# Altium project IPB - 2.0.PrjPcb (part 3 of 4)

## Sheet Anti_Alias_Filter.SchDoc: MARS2 - IPB - Anti-Alias Filter
size 431 x 279 mm; Organization: ORGANIZATION; Address1: APPLIED PHYSICS LAB; Address2: UNIVERSITY OF WASHINGTON; Address3: 1013 NE 40TH STREET; Address4: SEATTLE, WA 98105; Revision: -; SheetNumber: 18; SheetTotal: 23; ENG_APP_DATE: --/--/--; DSN_APP_DATE: --/--/--; CHK_APP_DATE: --/--/--
Used 4 times, as channels Designator/Interface Channel A/Anti-Alias Filter, Designator/Interface Channel B/Anti-Alias Filter, Designator/Interface Channel C/Anti-Alias Filter, Designator/Interface Channel D/Anti-Alias Filter. Parts and nets are listed once, with the designators drawn on the sheet.
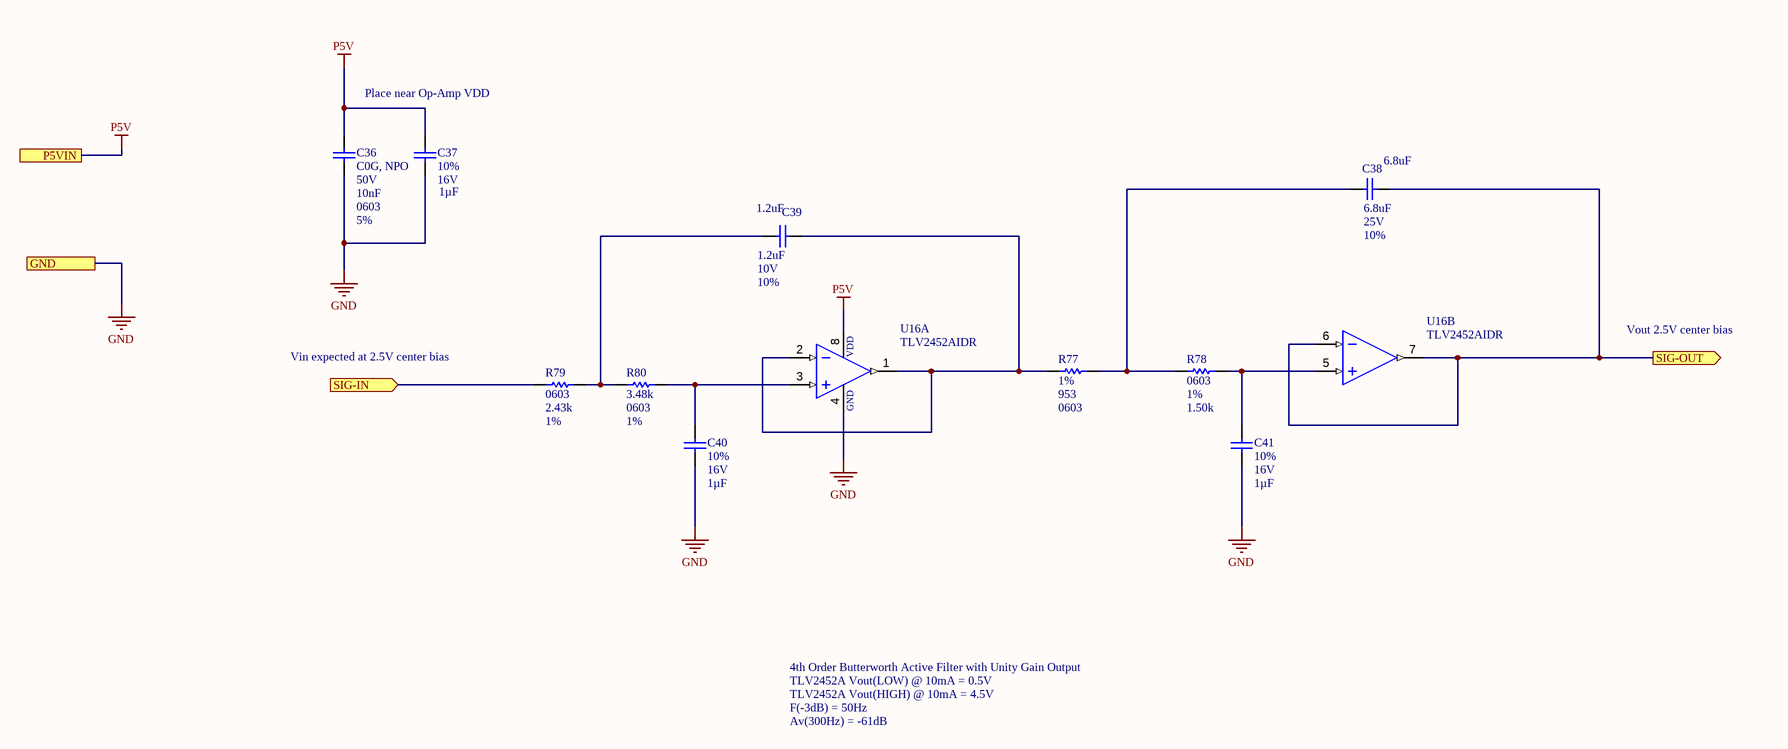
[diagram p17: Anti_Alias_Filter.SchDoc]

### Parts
C36  Dielectric: C0G, NPO  Voltage Rating: 50V  Capacitance: 10nF  Case/Package: 0603  Tolerance: 5%  [CAPC1608X90X40ML10T20]  (hidden comment: Capacitor 10nF +/- 5%, 50V, C0G, 0603)
C37  value 1µF  Tolerance: 10%  Voltage Rating: 16V  [CAPC1608X94X35NL15T15]  (hidden comment: Capacitor 1 uF +/- 10% 16 V 0603)
C38  value 6.8uF  Voltage Rating: 25V  Tolerance: 10%  Capacitance: 6.8uF  [FP-CGA5L-0_3-0_1-IPC_A]  (hidden comment: CGA5L1X7R1E685K160AC)
C39  value 1.2uF  Tolerance: 10%  Voltage Rating (DC): 10V  Capacitance: 1.2uF  [CAPC2012X11M]  (hidden comment: C0805C125K8RAC7800)
C40  value 1µF  Tolerance: 10%  Voltage Rating: 16V  [CAPC1608X94X35NL15T15]  (hidden comment: Capacitor 1 uF +/- 10% 16 V 0603)
C41  value 1µF  Tolerance: 10%  Voltage Rating: 16V  [CAPC1608X94X35NL15T15]  (hidden comment: Capacitor 1 uF +/- 10% 16 V 0603)
R77  value 953  Tolerance: 1%  Case/Package: 0603  [RESC1608X55X25ML10T15]  (hidden comment: Resistor 953R +/-1% 0603 100 mW)
R78  value 1.50k  Case/Package: 0603  Tolerance: 1%  [RESC1608X55X25ML10T15]  (hidden comment: Resistor 1K50+/-1% 0603 100 mW)
R79  value 2.43k  Case/Package: 0603  Tolerance: 1%  [RESC1608X55X25ML10T15]  (hidden comment: Resistor 2K43+/-1% 0603 100 mW)
R80  value 3.48k  Case/Package: 0603  Tolerance: 1%  [RESC1608X55X25ML10T15]  (hidden comment: Resistor 3K48+/-1% 0603 100 mW)
U16  TLV2452AIDR  [D0008A_L]  (parts A,B of 2)

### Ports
GND, P5VIN, SIG-IN (in), SIG-OUT (out)

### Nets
GND: C36.2 C37.1 C40.1 C41.1 U16.4(GND) ; port GND
P5V: C36.1 C37.2 U16.8(VDD+) ; port P5VIN
SIG-IN: R79.1 ; port SIG-IN
SIG-OUT: C38.1 U16.6(IN2-) U16.7(OUT2) ; port SIG-OUT
NetC38_2: C38.2 R77.2 R78.1
NetC39_1: C39.1 R79.2 R80.1
NetC39_2: C39.2 R77.1 U16.1(OUT1) U16.2(IN1-)
NetC40_2: C40.2 R80.2 U16.3(IN1+)
NetC41_2: C41.2 R78.2 U16.5(IN2+)

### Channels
Designator/Interface Channel A/Anti-Alias Filter: designators end in _A; ports GND=LV_GND P5VIN=LV_P5V SIG-IN=CH-I_Interface Channel A SIG-OUT=CHA_I
Designator/Interface Channel B/Anti-Alias Filter: designators end in _B; ports GND=LV_GND P5VIN=LV_P5V SIG-IN=CH-I_Interface Channel B SIG-OUT=CHB_I
Designator/Interface Channel C/Anti-Alias Filter: designators end in _C; ports GND=LV_GND P5VIN=LV_P5V SIG-IN=CH-I_Interface Channel C SIG-OUT=CHC_I
Designator/Interface Channel D/Anti-Alias Filter: designators end in _D; ports GND=LV_GND P5VIN=LV_P5V SIG-IN=CH-I_Interface Channel D SIG-OUT=CHD_I

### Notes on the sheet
- Place near Op-Amp VDD
- Vout 2.5V center bias
- Vin expected at 2.5V center bias
- 4th Order Butterworth Active Filter with Unity Gain Output
- TLV2452A Vout(LOW) @ 10mA = 0.5V
- TLV2452A Vout(HIGH) @ 10mA = 4.5V
- F(-3dB) = 50Hz
- Av(300Hz) = -61dB

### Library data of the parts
C36 = CMP-001-00166-10: Chip Capacitor, 10nF, +/- 5%, 50 V, C0G 0603 (1608 Metric); Capacitor Type: Ceramic
C37 C40 C41 = CMP-001-00003-15: Chip Capacitor, 1 uF, +/- 10%, 16 V, 0603 (1608 Metric); Capacitor Type: Ceramic; Decade: 1uF
C38 = CMP-001-00094-9: Cap Ceramic 6.8uF 25V X7R 10% SMD 1206 125°C Blister Plastic T/R; Manufacturer: TDK; Decade: 1uF
C39 = CMP-001-00093-9: Cap Ceramic 1.2uF 10V X7R 10% SMD 0805 125°C Plastic T/R; Manufacturer: KEMET; Decade: 1uF
R77 = CMP-009-00692-4: Chip Resistor, 953 Ohm, +/- 1%, 0.1 W, -55 to 155 degC, 0603 (1608 Metric); Decade: 100; Power: 100mW; Voltage Rating: 75V
R78 = CMP-009-00693-3: Chip Resistor, 1.50 KOhm, +/- 1%, 0.1 W, -55 to 155 degC, 0603 (1608 Metric); Voltage Rating: 75V; Decade: 1k; Power: 100mW
R79 = CMP-009-00594-3: Chip Resistor, 2.43 KOhm, +/- 1%, 0.1 W, -55 to 155 degC, 0603 (1608 Metric); Power: 100mW; Decade: 1k; Voltage Rating: 75V
R80 = CMP-009-00691-3: Chip Resistor, 3.48 KOhm, +/- 1%, 0.1 W, -55 to 155 degC, 0603 (1608 Metric); Decade: 1k; Power: 100mW; Voltage Rating: 75V
U16 = CMP-014-00006-4: TLV2452A Dual 23-UA 220-KHZ Rail; Gain Bandwidth Product: 220kHz; Input Bias Current: 5nA; Voltage Gain: 103dB; Max Supply Voltage: 6V; Max Power Dissipation: 710mW; Min Dual Supply Voltage: 1.35V; Slew Rate: 0.11V/µs; Min Supply Voltage: 2.7V; Output Current: 10mA; Max Dual Supply Voltage: 3V; Nominal Supply Current: 84uA; Number of Channels: 2; Amplifier Type: GENERAL PURPOSE; Common Mode Rejection Ratio: 70dB; Input Offset Voltage (Vos): 1mV

## Sheet Solid_State_Switch.SchDoc: MARS2 - IPB - HV Solid State Switches
size 431 x 279 mm; Address1: APPLIED PHYSICS LAB; Address2: UNIVERSITY OF WASHINGTON; Address3: 1013 NE 40TH STREET; Address4: SEATTLE, WA 98105; SheetNumber: 19; SheetTotal: 23; ENG_APP_DATE: --/--/--; DSN_APP_DATE: --/--/--; CHK_APP_DATE: --/--/--; SPICEModelCacheBYHFRFMZ: <root> / <DocumentId>BYHFRFMZ</DocumentId> / </root>
Used 4 times, as channels Designator/Interface Channel A/Solid State Switches, Designator/Interface Channel B/Solid State Switches, Designator/Interface Channel C/Solid State Switches, Designator/Interface Channel D/Solid State Switches. Parts and nets are listed once, with the designators drawn on the sheet.
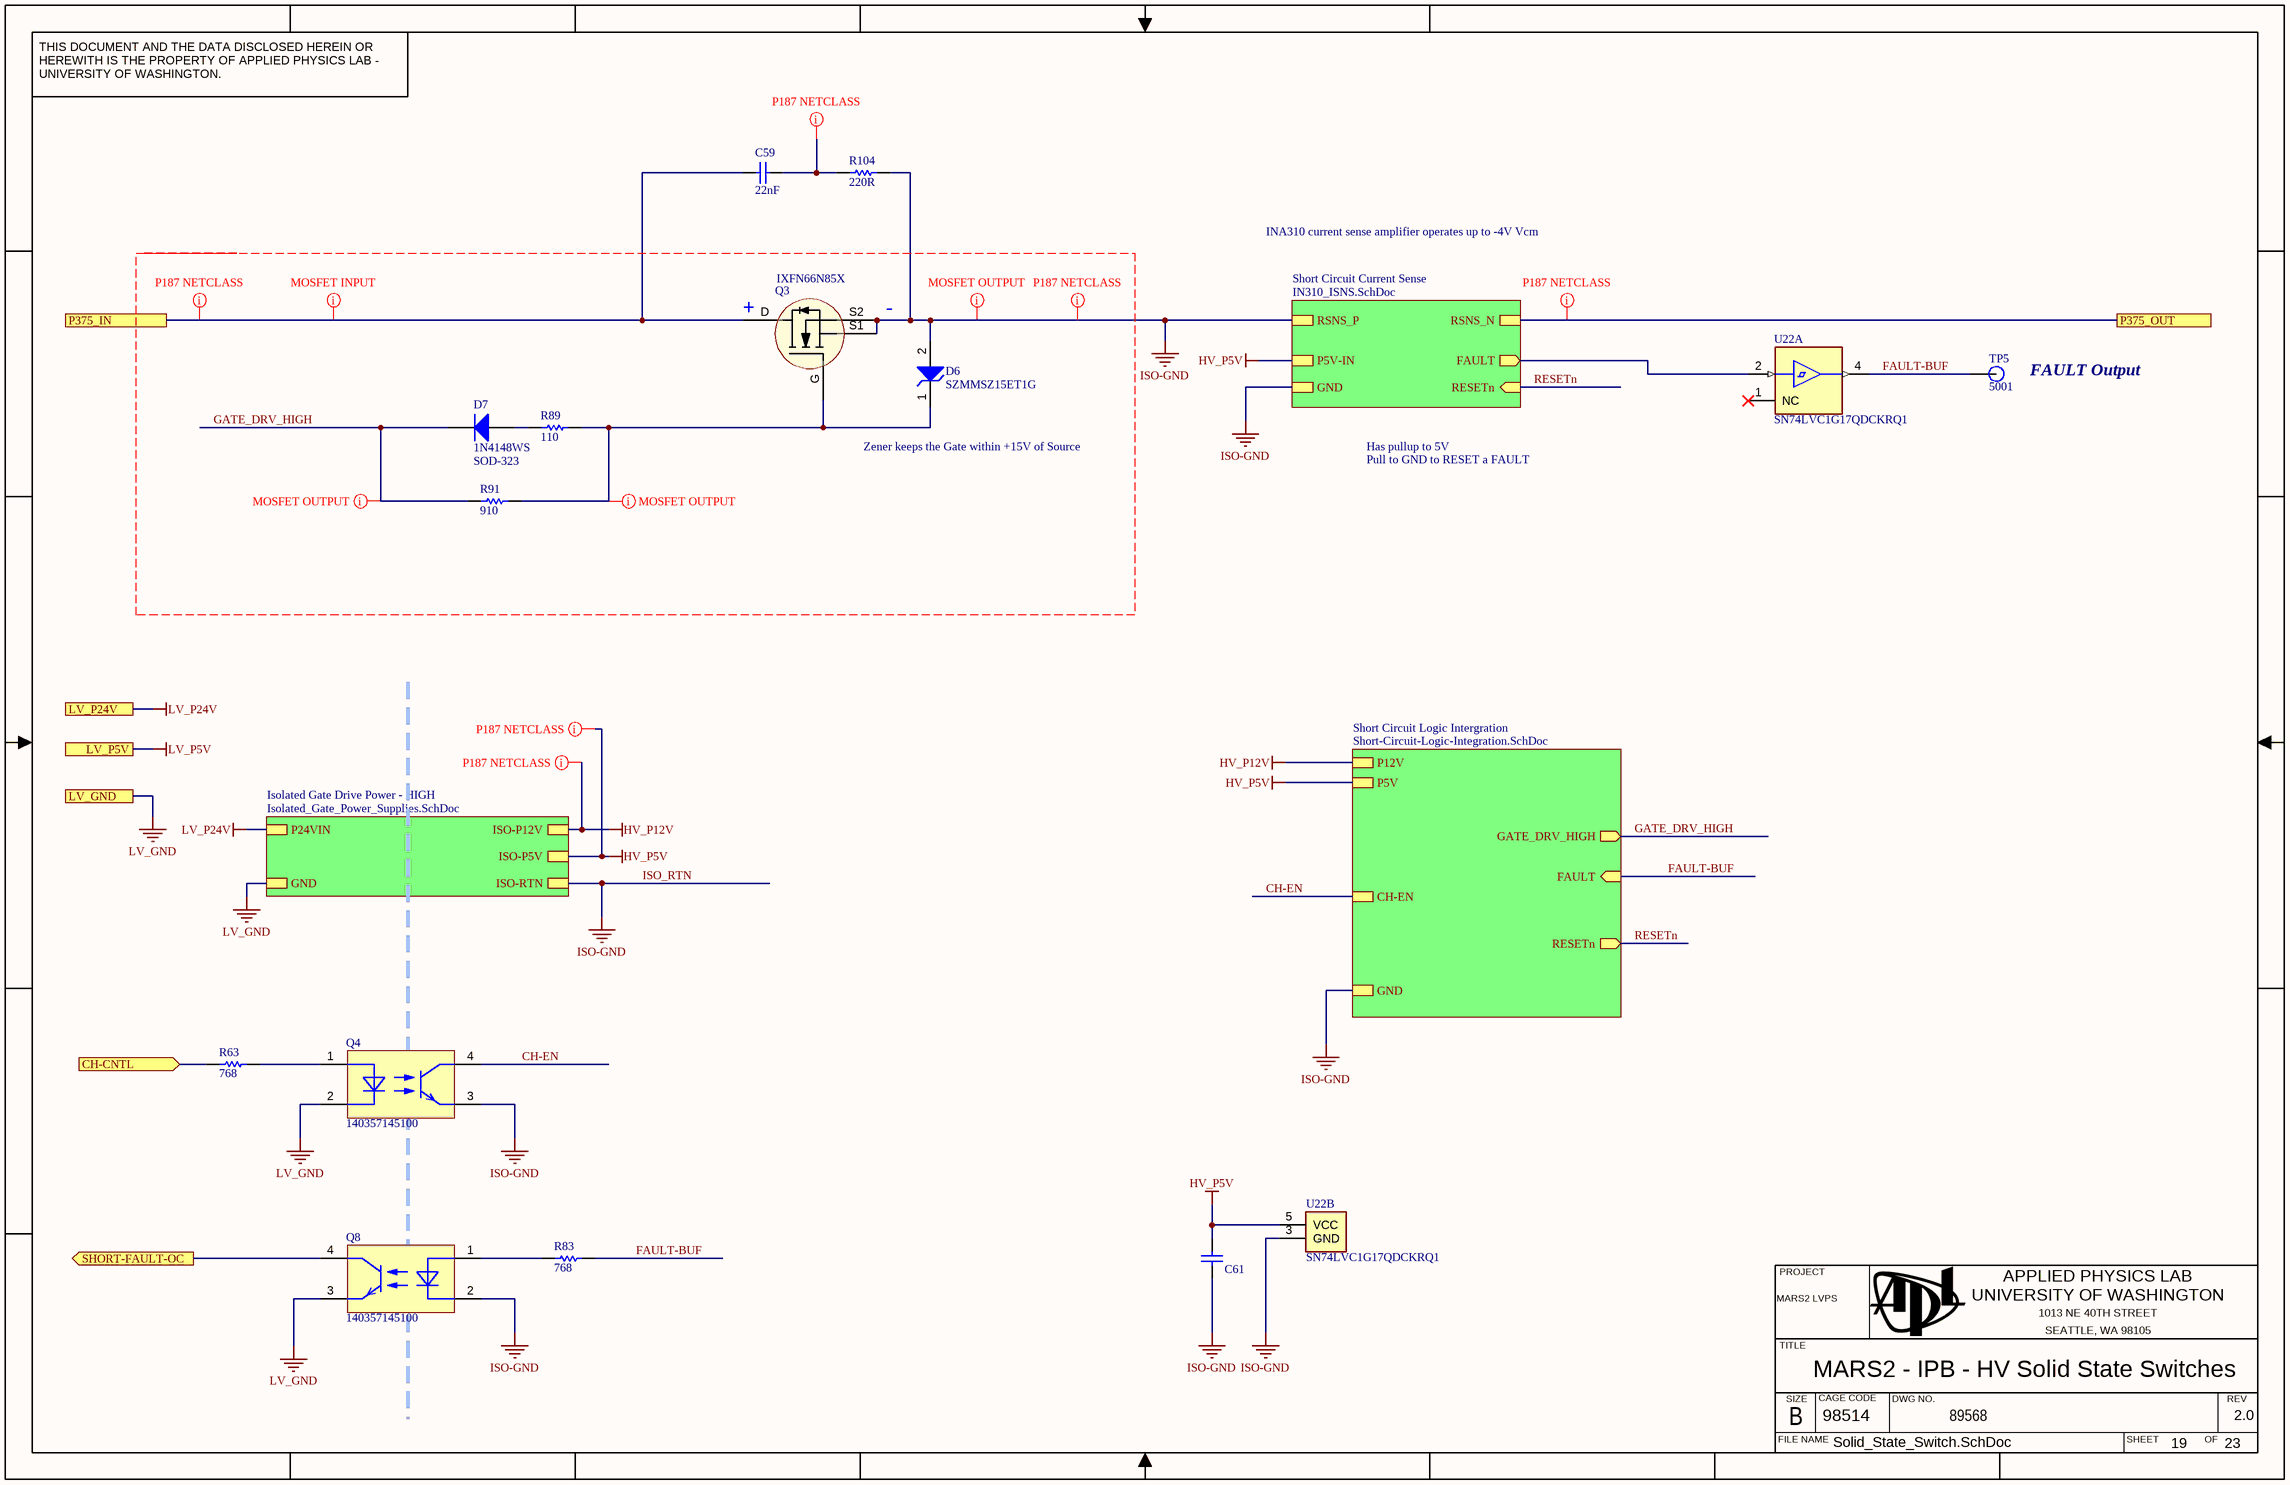
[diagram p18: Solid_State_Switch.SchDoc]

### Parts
C59  value 22nF  [R76QI222050H4J-Footprint-1]  (hidden comment: R76QI222050H4J)
C61  885012207072  [WCAP-CSGP_0805_L2W1.25H0.8_Reflow]  (value not drawn)
D6  SZMMSZ15ET1G  [ONSC-SOD-123-2-425-04_V]
D7  1N4148WS  Case/Package: SOD-323  [FAIR-SOD-323_V]
Q3  IXFN66N85X  [IXFN66N85X-Footprint-1]
Q4  140357145100  [WL-OCPT_SOP4]
Q8  140357145100  [WL-OCPT_SOP4]
R63  value 768  [PANASONIC_ERJ6E]  (hidden comment: RES 0805 768R 1%)
R83  value 768  [PANASONIC_ERJ6E]  (hidden comment: RES 0805 768R 1%)
R89  value 110  [PANASONIC_ERJ6E]  (hidden comment: RES 0805 110R 1%)
R91  value 910  [PANASONIC_ERJ6E]  (hidden comment: RES 0805 910R 1%)
R104  value 220R  [RESC3126X06M]  (hidden comment: RPC2010JT220R)
TP5  5001  [Keystone 5001]
U22  SN74LVC1G17QDCKRQ1  [FP-DCK0005A-MFG]  (parts A,B of 2)

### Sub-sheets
Isolated Gate Drive Power - HIGH = Isolated_Gate_Power_Supplies.SchDoc: ISO-RTN, ISO-P12V, ISO-P5V, GND, P24VIN
Short Circuit Current Sense = IN310_ISNS.SchDoc: RSNS_P, RSNS_N, P5V-IN, GND, FAULT (out), RESETn (in)
Short Circuit Logic Intergration = Short-Circuit-Logic-Integration.SchDoc: GND, P5V, RESETn (out), FAULT (in), P12V, GATE_DRV_HIGH (out), CH-EN

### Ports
CH-CNTL (in), LV_GND, LV_P5V, LV_P24V, P375_IN, P375_OUT, SHORT-FAULT-OC (out)

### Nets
HV_P5V: C61.2 U22.5(VCC) ; sheet Isolated Gate Drive Power - HIGH/ISO-P5V, sheet Short Circuit Current Sense/P5V-IN, sheet Short Circuit Logic Intergration/P5V
HV_P12V: sheet Isolated Gate Drive Power - HIGH/ISO-P12V, sheet Short Circuit Logic Intergration/P12V
ISO_RTN: C61.1 D6.2(A) Q3.S1 Q3.S2 Q4.3(Emitter) Q8.2(Cathode) R104.2 U22.3(GND) ; sheet Isolated Gate Drive Power - HIGH/ISO-RTN, sheet Short Circuit Current Sense/RSNS_P, sheet Short Circuit Current Sense/GND, sheet Short Circuit Logic Intergration/GND  [also labelled ISO-GND]
LV_GND: Q4.2(Cathode) Q8.3(Emitter) ; port LV_GND, sheet Isolated Gate Drive Power - HIGH/GND
LV_P24V: port LV_P24V, sheet Isolated Gate Drive Power - HIGH/P24VIN
CH-CNTL: R63.1 ; port CH-CNTL
CH-EN: Q4.4(Collector) ; sheet Short Circuit Logic Intergration/CH-EN
FAULT-BUF: R83.2 TP5.1 U22.4(Y) ; sheet Short Circuit Logic Intergration/FAULT
GATE_DRV_HIGH: D7.2(K) R91.1 ; sheet Short Circuit Logic Intergration/GATE_DRV_HIGH
P375_IN: C59.1 Q3.D ; port P375_IN
P375_OUT: port P375_OUT, sheet Short Circuit Current Sense/RSNS_N
RESETn: sheet Short Circuit Current Sense/RESETn, sheet Short Circuit Logic Intergration/RESETn
SHORT-FAULT-OC: Q8.4(Collector) ; port SHORT-FAULT-OC
NetC59_2: C59.2 R104.1
NetD6_1: D6.1(K) Q3.G R89.2 R91.2
NetD7_1: D7.1(A) R89.1
NetQ4_1: Q4.1(Anode) R63.2
NetQ8_1: Q8.1(Anode) R83.1
NetU22_2: U22.2(A) ; sheet Short Circuit Current Sense/FAULT

Not connected (* = marked no-connect by the designer): U22 1(NC)*

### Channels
Designator/Interface Channel A/Solid State Switches: designators end in _A; ports CH-CNTL=NetR63_A_1 LV_GND=LV_GND LV_P5V=LV_P5V LV_P24V=COIL_DRV_HIGH P375_IN=NetC59_A_1 P375_OUT=NetD8_A_2 SHORT-FAULT-OC=FAULT-INJECT_Interface Channel A
Designator/Interface Channel B/Solid State Switches: designators end in _B; ports CH-CNTL=NetR63_B_1 LV_GND=LV_GND LV_P5V=LV_P5V LV_P24V=COIL_DRV_HIGH P375_IN=NetC59_B_1 P375_OUT=NetD8_B_2 SHORT-FAULT-OC=FAULT-INJECT_Interface Channel B
Designator/Interface Channel C/Solid State Switches: designators end in _C; ports CH-CNTL=NetR63_C_1 LV_GND=LV_GND LV_P5V=LV_P5V LV_P24V=COIL_DRV_HIGH P375_IN=NetC59_C_1 P375_OUT=NetD8_C_2 SHORT-FAULT-OC=FAULT-INJECT_Interface Channel C
Designator/Interface Channel D/Solid State Switches: designators end in _D; ports CH-CNTL=NetR63_D_1 LV_GND=LV_GND LV_P5V=LV_P5V LV_P24V=COIL_DRV_HIGH P375_IN=NetC59_D_1 P375_OUT=NetD8_D_2 SHORT-FAULT-OC=FAULT-INJECT_Interface Channel D

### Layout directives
net class P187_REF: HV_P5V, HV_P12V, ISO_RTN_Solid State Switches, NetC59_A_1, NetC59_A_2, NetD8_A_2
net class MOSFET OUTPUT: GATE_DRV_HIGH_Solid State Switches, ISO_RTN_Solid State Switches, NetD6_A_1
net class MOSFET INPUT: NetC59_A_1

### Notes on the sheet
- (near Q3) +
- -
- INA310 current sense amplifier operates up to -4V Vcm
- (near TP5) FAULT Output
- Zener keeps the Gate within +15V of Source
- Has pullup to 5V
- Pull to GND to RESET a FAULT

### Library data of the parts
C59 = CMP-001-00247-2: Double Metallized Polypropylene Film Capacitor; Lead/Base Style: Straight; Voltage Rating (AC): 600V; Tolerance: 5%; Lead Diameter: 1mm; Dielectric: PP; Voltage Rating: 1kV
C61 = CMP-118-000468-2: WCAP-CSGP Multilayer Ceramic Chip Capacitor, General Purpose, size 0805, X7R, 100nF, 25VDC; Manufacturer: Wurth Elektronik; Dissipation Factor: 3.5%; Rated Voltage (DC): 25V; Capacitance Tolerance: +/-10%; Insulation Resistance: 5GOhm; Case/Size Code: 0805; Technical Reference: X7R0805104K025DFCT10000
D6 = CMP-004-00039-2: Diode Zener Single 15V 5% 500mW Automotive 2-Pin SOD-123 T/R; Max Reverse Leakage Current: 50nA
D7 = CMP-004-00001-3: Small Signal Diode, 75 V, 0.15 A, -55 to 150 degC, 2-Pin SOD-323, RoHS, Tape and Reel; Manufacturer: Fairchild; Recovery Time: 4ns; Forward Voltage: 1V; Peak Reverse Current: 5uA; Forward Current: 150mA; Capacitance: -323f
Q3 = CMP-013-00040-7: Trans MOSFET N-CH 850V 65A 4-Pin SOT-227B; Transistor Type: NMOS
Q4 Q8 = CMP-00026-00003-3: Optocoupler, Transistor, 35V, Sop-4 Rohs Compliant: Yes
R63 R83 = CMP-009-01863-3: Generic 1% 768 Ohm 0805 Resistor; Decade: 100; Power: 0.125W; Voltage Rating: 150V
R89 = CMP-009-01766-3: Generic 1% 110 Ohm 0805 Resistor; Power: 0.125W; Decade: 100; Voltage Rating: 150V
R91 = CMP-009-01752-3: Generic 1% 910 Ohm 0805 Resistor; Voltage Rating: 150V; Decade: 100; Power: 0.125W
R104 = CMP-009-02043-1: Res Thick Film 2010 220 Ohm 5% 3/4W ±100ppm/°C Molded SMD SMD Paper T/R; Max Power Dissipation: 750mW
TP5 = CMP-001-0002-14: PC TEST POINT MINIATURE BLACK; Manufacturer: Keystone
U22 = CMP-016-00010-2: Automotive single 1.65-V to 6.5-V buffer with Schmitt-Trigger inputs 5-SC70 -40 to 125; Quiescent Current: 20uA; Min Supply Voltage: 1.65V; Number of Channels: 1; Output Type: PUSH-PULL; Turn-On Delay Time: 14ns; Logic Function: Schmitt Trigger,Buffer,Inverting; Max Supply Voltage: 5.5V; Propagation Delay: 8ns; Polarity: Non-Inverting

## Sheet Isolated_Gate_Power_Supplies.SchDoc: MARS2 - IPB - HV ISO Gate PSU
size 431 x 279 mm; Organization: ORGANIZATION; Address1: APPLIED PHYSICS LAB; Address2: UNIVERSITY OF WASHINGTON; Address3: 1013 NE 40TH STREET; Address4: SEATTLE, WA 98105; Revision: -; SheetNumber: 20; SheetTotal: 23; ENG_APP_DATE: --/--/--; DSN_APP_DATE: --/--/--; CHK_APP_DATE: --/--/--
Used 4 times, as channels Designator/Interface Channel A/Solid State Switches/Isolated Gate Drive Power - HIGH, Designator/Interface Channel B/Solid State Switches/Isolated Gate Drive Power - HIGH, Designator/Interface Channel C/Solid State Switches/Isolated Gate Drive Power - HIGH, Designator/Interface Channel D/Solid State Switches/Isolated Gate Drive Power - HIGH. Parts and nets are listed once, with the designators drawn on the sheet.
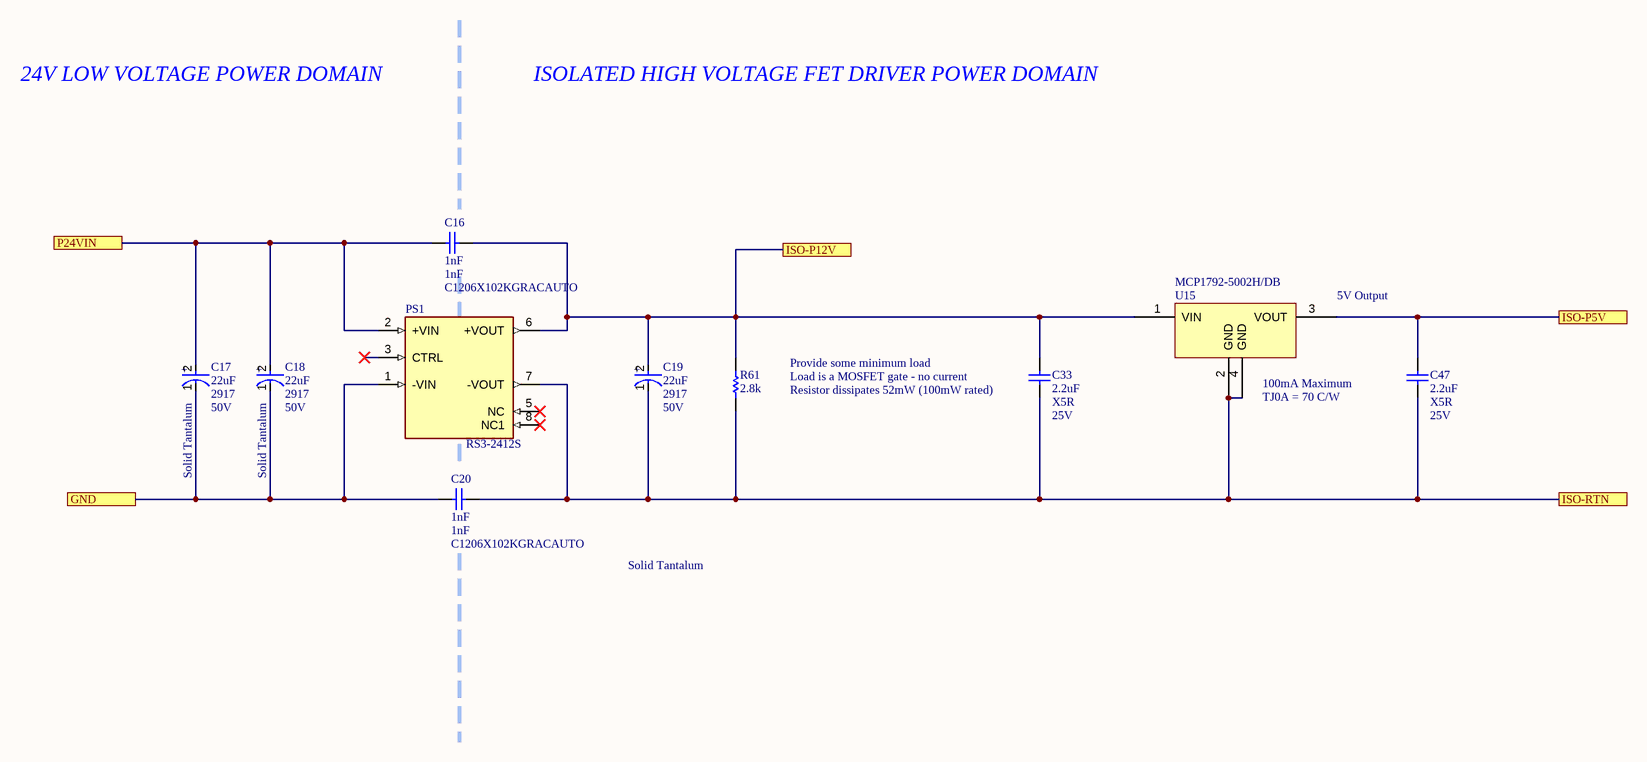
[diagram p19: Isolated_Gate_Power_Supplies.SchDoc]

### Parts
C16  C1206X102KGRACAUTO  value 1nF  Capacitance: 1nF  [FP-C1206X102KGRACAUTO-IPC_A]
C17  value 22uF  Case/Package: 2917  Voltage Rating: 50V  [FP-T491X226K050AT-MFG]  (hidden comment: T491X226K050AT)
C18  value 22uF  Case/Package: 2917  Voltage Rating: 50V  [FP-T491X226K050AT-MFG]  (hidden comment: T491X226K050AT)
C19  value 22uF  Case/Package: 2917  Voltage Rating: 50V  [FP-T491X226K050AT-MFG]  (hidden comment: T491X226K050AT)
C20  C1206X102KGRACAUTO  value 1nF  Capacitance: 1nF  [FP-C1206X102KGRACAUTO-IPC_A]
C33  Capacitance: 2.2uF  Ceramic Type: X5R  Rated Voltage (DC): 25V  [WCAP-CSGP_0805_L2W1.25H1.25]  (hidden comment: 885012107016)
C47  Capacitance: 2.2uF  Ceramic Type: X5R  Rated Voltage (DC): 25V  [WCAP-CSGP_0805_L2W1.25H1.25]  (hidden comment: 885012107016)
PS1  RS3-2412S  [CONV_RS3-2412S]
R61  value 2.8k  [RESC1609X50X30ML08T20]  (hidden comment: Resistor 2K80 +/-1% 0603 100 mW)
U15  MCP1792-5002H/DB  [SOT230P700X180-4M]

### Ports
GND, ISO-P5V, ISO-P12V, ISO-RTN, P24VIN

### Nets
GND: C17.1(C) C18.1(C) C20.1 PS1.1(-VIN) ; port GND
ISO-P5V: C47.2 U15.3(VOUT) ; port ISO-P5V
ISO-P12V: C16.2 C19.2(A) C33.2 PS1.6(+VOUT) R61.2 U15.1(VIN) ; port ISO-P12V
ISO-RTN: C19.1(C) C20.2 C33.1 C47.1 PS1.7(-VOUT) R61.1 U15.2(GND) U15.4(GND) ; port ISO-RTN
P24VIN: C16.1 C17.2(A) C18.2(A) PS1.2(+VIN) ; port P24VIN

Not connected (* = marked no-connect by the designer): PS1 3(CTRL)* 5(NC)* 8(NC1)*

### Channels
Designator/Interface Channel A/Solid State Switches/Isolated Gate Drive Power - HIGH: designators end in _A; ports GND=LV_GND ISO-P5V=HV_P5V ISO-P12V=HV_P12V ISO-RTN=ISO_RTN_Solid State Switches P24VIN=COIL_DRV_HIGH
Designator/Interface Channel B/Solid State Switches/Isolated Gate Drive Power - HIGH: designators end in _B; ports GND=LV_GND ISO-P5V=HV_P5V ISO-P12V=HV_P12V ISO-RTN=ISO_RTN_Solid State Switches P24VIN=COIL_DRV_HIGH
Designator/Interface Channel C/Solid State Switches/Isolated Gate Drive Power - HIGH: designators end in _C; ports GND=LV_GND ISO-P5V=HV_P5V ISO-P12V=HV_P12V ISO-RTN=ISO_RTN_Solid State Switches P24VIN=COIL_DRV_HIGH
Designator/Interface Channel D/Solid State Switches/Isolated Gate Drive Power - HIGH: designators end in _D; ports GND=LV_GND ISO-P5V=HV_P5V ISO-P12V=HV_P12V ISO-RTN=ISO_RTN_Solid State Switches P24VIN=COIL_DRV_HIGH

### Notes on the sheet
- 24V LOW VOLTAGE POWER DOMAIN
- ISOLATED HIGH VOLTAGE FET DRIVER POWER DOMAIN
- (near U15) 5V Output
- (near C33) Resistor dissipates 52mW (100mW rated)
- Load is a MOSFET gate - no current
- Provide some minimum load
- (near U15) 100mA Maximum
- (near U15) TJ0A = 70 C/W
- (near C17) Solid Tantalum
- (near C18) Solid Tantalum
- Solid Tantalum

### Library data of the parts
C16 C20 = CMP-001-00212-10: Cap Ceramic 0.001uF 2000V X7R 10% Pad SMD 1206 Flexible Termination 125C Low ESR Automotive T/R; Manufacturer: KEMET; Voltage Rating: 2kV
C17-C19 = CMP-001-00083-12: Cap Tant Solid 22uF 50V X CASE 10% (7.3 X 4.3 X 4mm) SMD 7343-43 0.6 Ohm 125 C T/R; Manufacturer: KEMET; ESR (Equivalent Series Resistance): 600mR; Test: Delete Me; Decade: 10uF
C33 C47 = CMP-118-000238-3: WCAP-CSGP Multilayer Ceramic Chip Capacitor, General Purpose, size 0805, X5R, 2.2uF, 25VDC; Manufacturer: Wurth Elektronik; Insulation Resistance: 0.05GOhm; Technical Reference: X5R0805225M025DFCT10000; Case/Size Code: 0805; Capacitance Tolerance: +/-20%; Dissipation Factor: 10%
PS1 = CMP-167-000000-3: 3W DC/DC-Converter 'ECONOLINE' SIP8 1kV reg 2:1; Manufacturer: Recom Power; Maximum Input Voltage: 36V; Minimum Input Voltage: 18V; Vout: 12V; Max Output current: 250mA; Isolation: Isolated; Number of Outputs: 1
R61 = CMP-009-00827-5: Chip Resistor, 2.8k Ohm, +/- 1%, 0.1 W, -55 to 155 degC, 0603 (1608 Metric); Decade: 1k; Power: 100mW; Voltage Rating: 75V
U15 = CMP-019-00076-3: High input voltage regulator 5.0 V 3Ld SOT-223 3 SOT-223 TUBE RoHS Compliant: Yes; Min Input Voltage: 6.2V; Max Input Voltage: 55V; Max Ouput Current: 100mA; Dropout Voltage: 1.2V

## Sheet IN310_ISNS.SchDoc
size 431 x 279 mm; Organization: ORGANIZATION; Address1: APPLIED PHYSICS LAB; Address2: UNIVERSITY OF WASHINGTON; Address3: 1013 NE 40TH STREET; Address4: SEATTLE, WA 98105; SheetTitle: INA310 Latching Current Sense Amplifier; Revision: -; SheetNumber: 21; SheetTotal: 23; ENG_APP_DATE: --/--/--; DSN_APP_DATE: --/--/--; CHK_APP_DATE: --/--/--; SPICEModelCacheSNWLCGMH: <root> / <DocumentId>SNWLCGMH</DocumentId> / </root>
Used 4 times, as channels Designator/Interface Channel A/Solid State Switches/Short Circuit Current Sense, Designator/Interface Channel B/Solid State Switches/Short Circuit Current Sense, Designator/Interface Channel C/Solid State Switches/Short Circuit Current Sense, Designator/Interface Channel D/Solid State Switches/Short Circuit Current Sense. Parts and nets are listed once, with the designators drawn on the sheet.
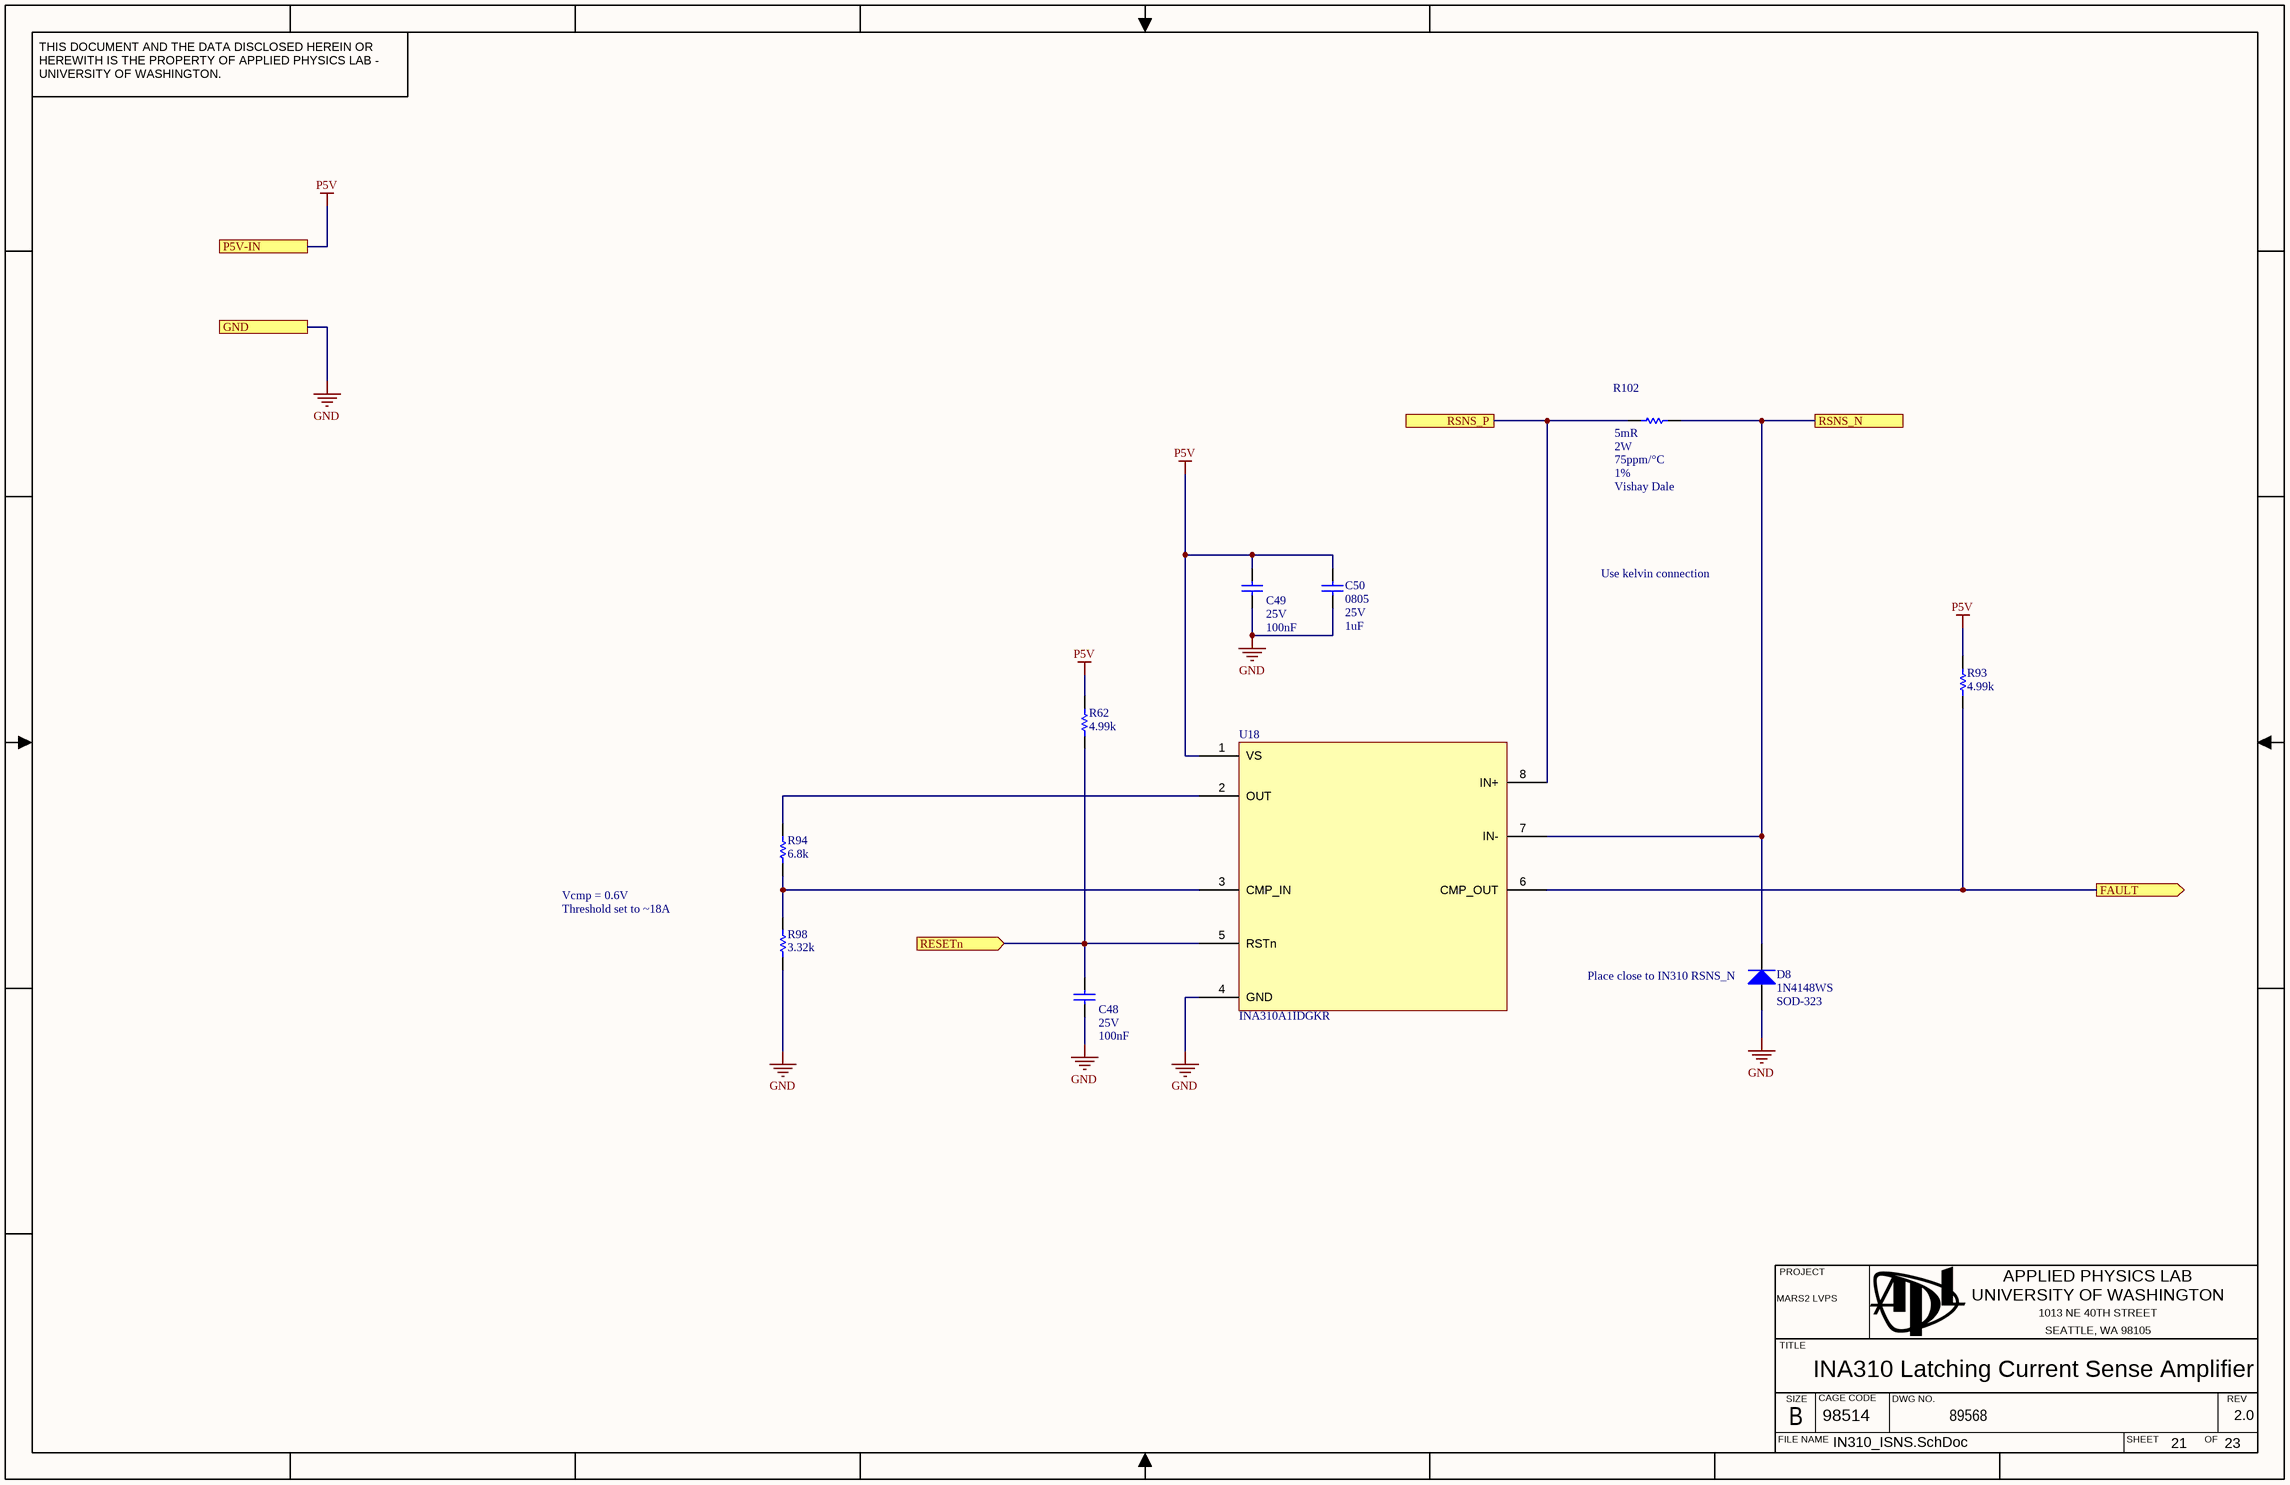
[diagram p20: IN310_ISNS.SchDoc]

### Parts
C48  Capacitance: 100nF  Rated Voltage (DC): 25V  [WCAP-CSGP_0805_L2W1.25H0.8_Reflow]  (hidden comment: 885012207072)
C49  Capacitance: 100nF  Rated Voltage (DC): 25V  [WCAP-CSGP_0805_L2W1.25H0.8_Reflow]  (hidden comment: 885012207072)
C50  Case/Size Code: 0805  Rated Voltage (DC): 25V  Capacitance: 1uF  [WCAP-CSGP_0805_L2W1.25H1.25]  (hidden comment: 885012107015)
D8  1N4148WS  Case/Package: SOD-323  [FAIR-SOD-323_V]
R62  value 4.99k  [PANASONIC_ERJ6E]  (hidden comment: RES 0805 4K99 1%)
R93  value 4.99k  [PANASONIC_ERJ6E]  (hidden comment: RES 0805 4K99 1%)
R94  value 6.8k  [PANASONIC_ERJ6E]  (hidden comment: RES 0805 6K80 1%)
R98  value 3.32k  [PANASONIC_ERJ6E]  (hidden comment: RES 0805 3K32 1%)
R102  value 5mR  Max Power Dissipation: 2W  Temperature Coefficient: 75ppm/°C  Tolerance: 1%  MF: Vishay Dale  [RESC7142X88N]  (hidden comment: WSL28165L000FEH)
U18  INA310A1IDGKR  [INA310]

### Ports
FAULT (out), GND, P5V-IN, RESETn (in), RSNS_N, RSNS_P

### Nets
GND: C48.1 C49.1 C50.1 D8.1(A) R98.1 U18.4(GND) ; port GND
P5V: C49.2 C50.2 R62.2 R93.2 U18.1(VS) ; port P5V-IN
FAULT: R93.1 U18.6(CMP_OUT) ; port FAULT
RESETn: C48.2 R62.1 U18.5(RSTn) ; port RESETn
RSNS_N: D8.2(K) R102.2 U18.7(IN-) ; port RSNS_N
RSNS_P: R102.1 U18.8(IN+) ; port RSNS_P
NetR94_1: R94.1 R98.2 U18.3(CMP_IN)
NetR94_2: R94.2 U18.2(OUT)

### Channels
Designator/Interface Channel A/Solid State Switches/Short Circuit Current Sense: designators end in _A; ports FAULT=NetR93_A_1 GND=ISO_RTN_Solid State Switches P5V-IN=HV_P5V RESETn=RESETn_Solid State Switches RSNS_N=NetD8_A_2 RSNS_P=ISO_RTN_Solid State Switches
Designator/Interface Channel B/Solid State Switches/Short Circuit Current Sense: designators end in _B; ports FAULT=NetR93_B_1 GND=ISO_RTN_Solid State Switches P5V-IN=HV_P5V RESETn=RESETn_Solid State Switches RSNS_N=NetD8_B_2 RSNS_P=ISO_RTN_Solid State Switches
Designator/Interface Channel C/Solid State Switches/Short Circuit Current Sense: designators end in _C; ports FAULT=NetR93_C_1 GND=ISO_RTN_Solid State Switches P5V-IN=HV_P5V RESETn=RESETn_Solid State Switches RSNS_N=NetD8_C_2 RSNS_P=ISO_RTN_Solid State Switches
Designator/Interface Channel D/Solid State Switches/Short Circuit Current Sense: designators end in _D; ports FAULT=NetR93_D_1 GND=ISO_RTN_Solid State Switches P5V-IN=HV_P5V RESETn=RESETn_Solid State Switches RSNS_N=NetD8_D_2 RSNS_P=ISO_RTN_Solid State Switches

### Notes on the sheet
- Use kelvin connection
- Vcmp = 0.6V
- Threshold set to
  8A
- (near D8) Place close to IN310 RSNS_N

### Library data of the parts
C48 C49 = CMP-118-000468-2: WCAP-CSGP Multilayer Ceramic Chip Capacitor, General Purpose, size 0805, X7R, 100nF, 25VDC; Manufacturer: Wurth Elektronik; Capacitance Tolerance: +/-10%; Dissipation Factor: 3.5%; Insulation Resistance: 5GOhm; Case/Size Code: 0805; Technical Reference: X7R0805104K025DFCT10000
C50 = CMP-118-000237-3: WCAP-CSGP Multilayer Ceramic Chip Capacitor, General Purpose, size 0805, X5R, 1uF, 25VDC; Manufacturer: Wurth Elektronik; Capacitance Tolerance: +/-20%; Insulation Resistance: 0.5GOhm; Dissipation Factor: 5%; Technical Reference: X5R0805105M025DFCT10000
D8 = CMP-004-00001-3: as D7 on sheet Solid_State_Switch
R62 R93 = CMP-009-01342-2: Generic 1% 4.99 kOhm 0805 Resistor; Decade: 1K; Power: 0.125W; Voltage Rating: 150V
R94 = CMP-009-01358-3: Generic 1% 6.8 kOhm 0805 Resistor; Decade: 1K; Power: 0.125W; Voltage Rating: 150V
R98 = CMP-009-01321-2: Generic 1% 3.32 kOhm 0805 Resistor; Decade: 1K; Power: 0.125W; Voltage Rating: 150V
R102 = CMP-009-02041-2: 5 mOhms 1% 2W Chip Current Sense Resistor Nonstandard Anti-Sulfur, Automotive AEC-Q200, Current Sense, Moisture Resistant, Pulse Withstanding Metal Element; Decade: 1m
U18 = CMP-014-00037-3: Current-sense amplifier 20V/V with latching comparator 8-VSSOP -40 to 125C, -4-V to 110-V, 1.3-MHz, ultra-precise.; Max Input Voltage: 20V; Max Common Mode Voltage: 110V; Min Input Voltage: 2.7V

## Sheet Short-Circuit-Logic-Integration.SchDoc
size 431 x 279 mm; SPICEModelCacheWKYXKNFH: <root> / <DocumentId>WKYXKNFH</DocumentId> / </root>; Organization: ORGANIZATION; Address1: APPLIED PHYSICS LAB; Address2: UNIVERSITY OF WASHINGTON; Address3: 1013 NE 40TH STREET; Address4: SEATTLE, WA 98105; SheetTitle: Short Circuit System Integration; Revision: -; SheetNumber: 22; SheetTotal: 23; ENG_APP_DATE: --/--/--; DSN_APP_DATE: --/--/--; CHK_APP_DATE: --/--/--
Used 4 times, as channels Designator/Interface Channel A/Solid State Switches/Short Circuit Logic Intergration, Designator/Interface Channel B/Solid State Switches/Short Circuit Logic Intergration, Designator/Interface Channel C/Solid State Switches/Short Circuit Logic Intergration, Designator/Interface Channel D/Solid State Switches/Short Circuit Logic Intergration. Parts and nets are listed once, with the designators drawn on the sheet.
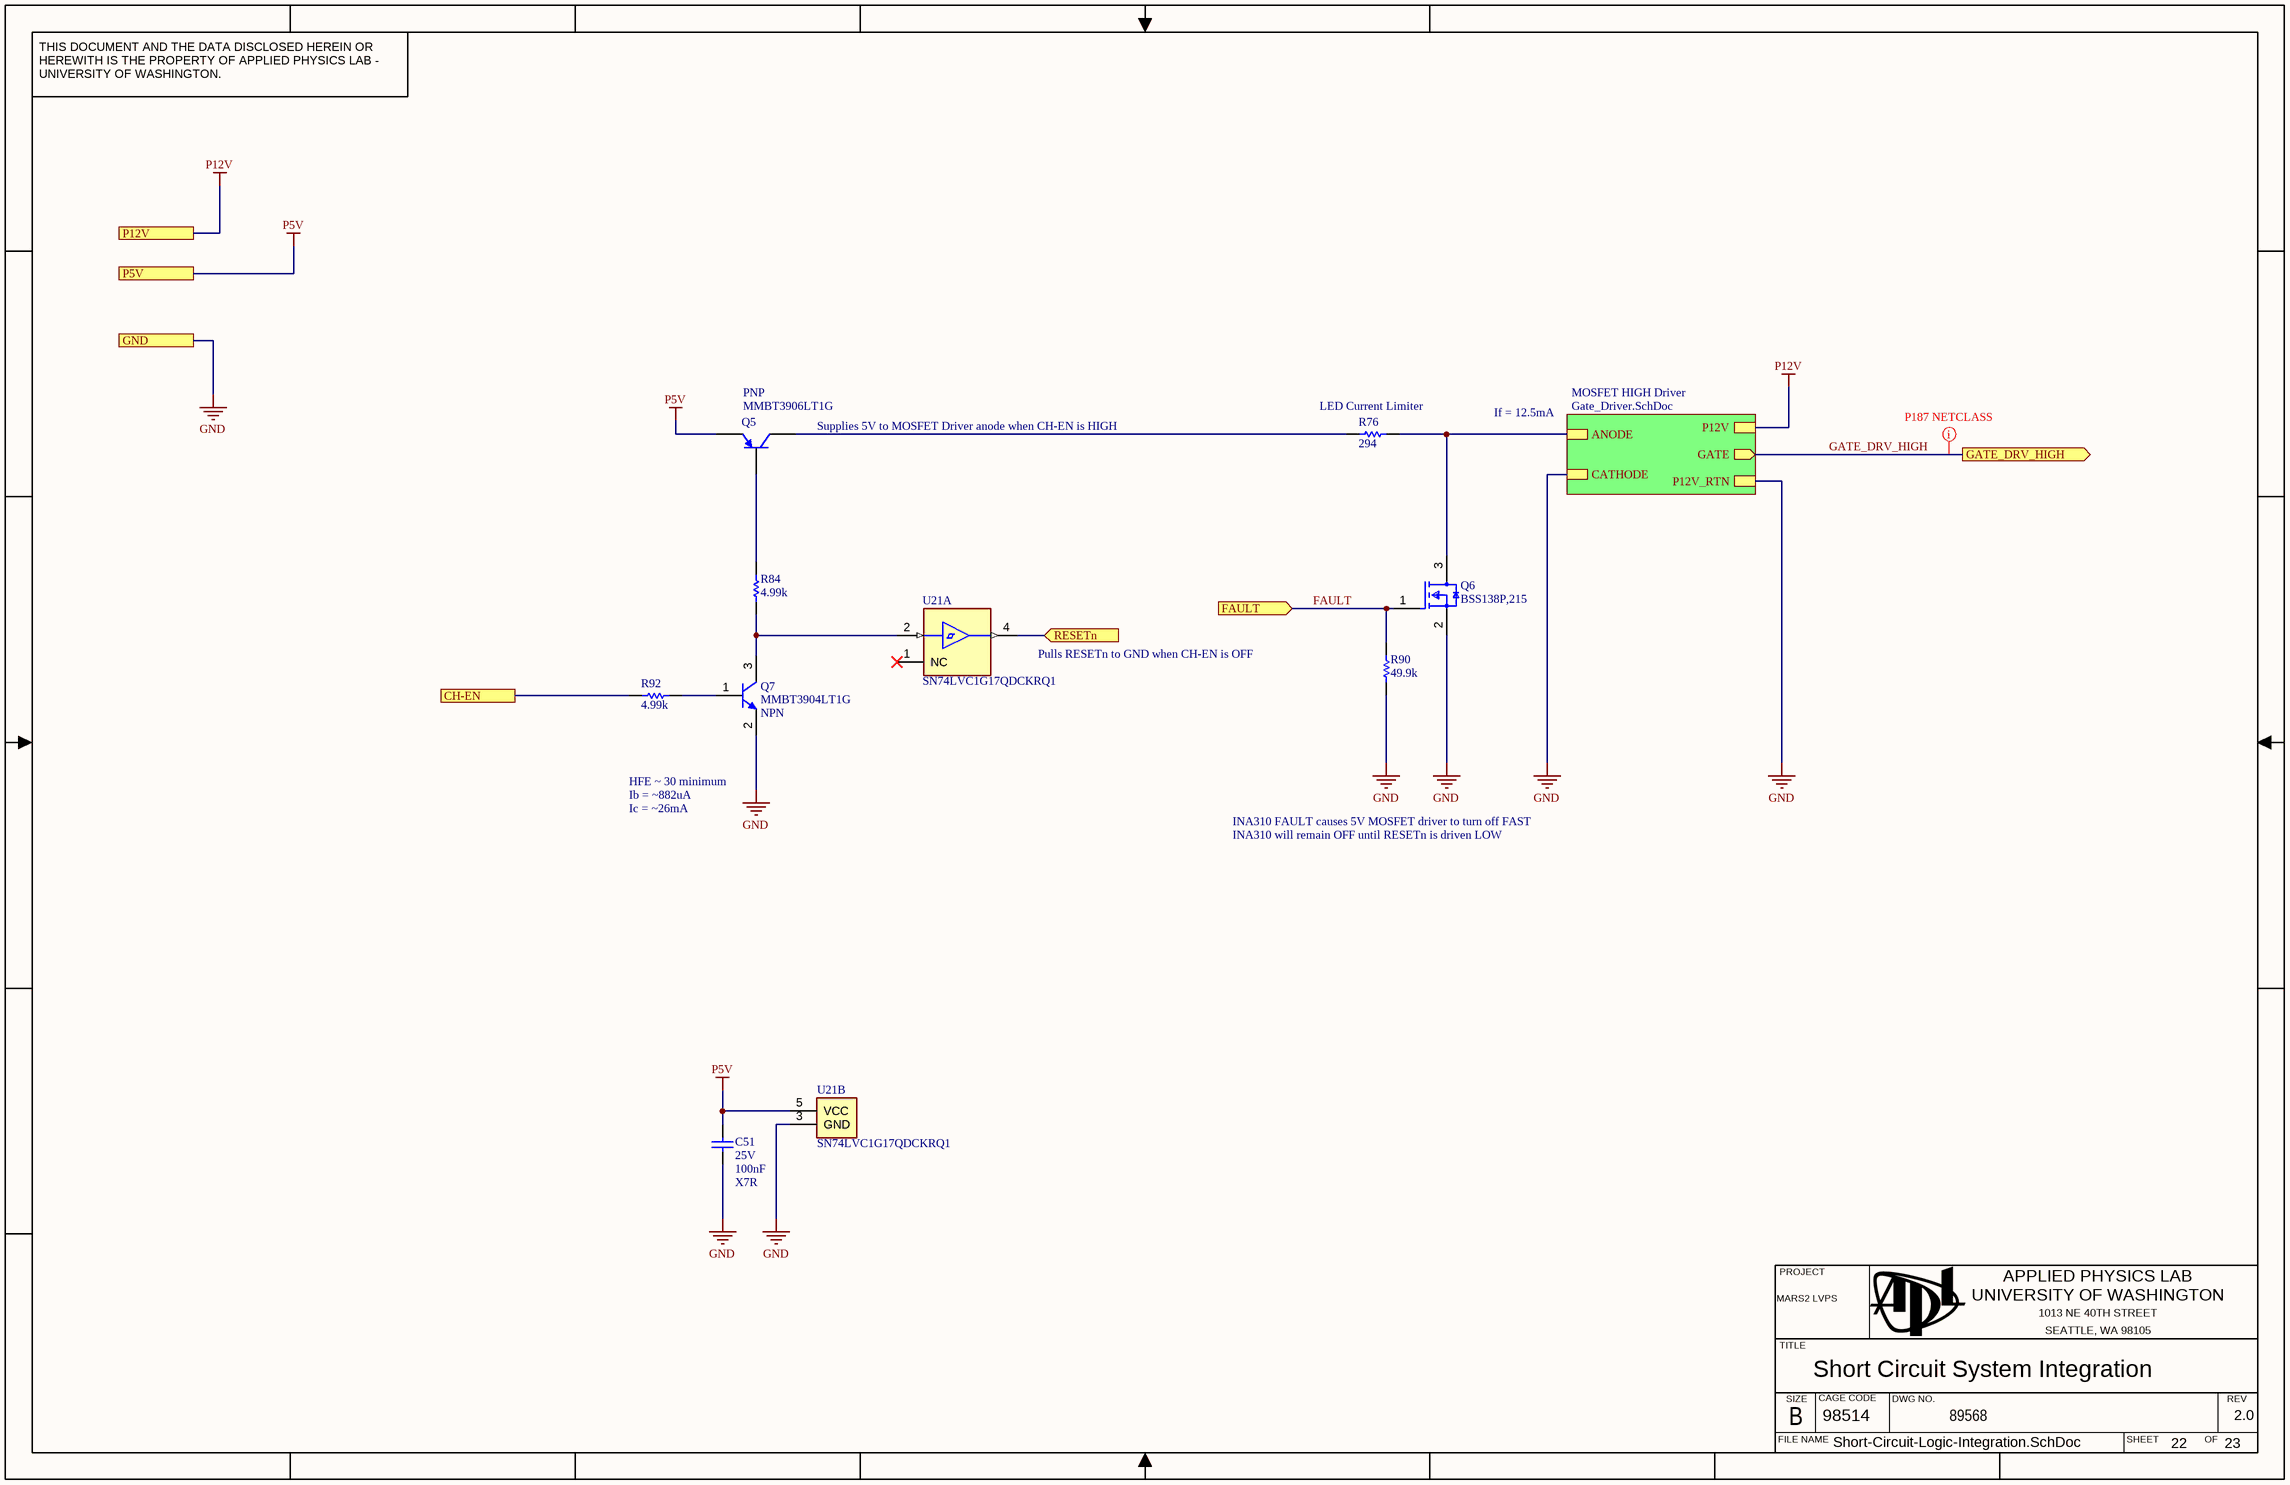
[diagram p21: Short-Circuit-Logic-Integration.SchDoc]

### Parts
C51  Rated Voltage (DC): 25V  Capacitance: 100nF  Ceramic Type: X7R  [WCAP-CSGP_0805_L2W1.25H0.8_Reflow]  (hidden comment: 885012207072)
Q5  MMBT3906LT1G  Transistor Type: PNP  [SOT95P237X111-3M]
Q6  BSS138P,215  [FP-SOT23-IPC_A]
Q7  MMBT3904LT1G  Transistor Type: NPN  [SOT95P237X111-3M]
R76  value 294  [PANASONIC_ERJ6E]  (hidden comment: RES 0805 294R 1%)
R84  value 4.99k  [PANASONIC_ERJ6E]  (hidden comment: RES 0805 4K99 1%)
R90  value 49.9k  [PANASONIC_ERJ6E]  (hidden comment: RES 0805 49K9 1%)
R92  value 4.99k  [PANASONIC_ERJ6E]  (hidden comment: RES 0805 4K99 1%)
U21  SN74LVC1G17QDCKRQ1  [FP-DCK0005A-MFG]  (parts A,B of 2)

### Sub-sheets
MOSFET HIGH Driver = Gate_Driver.SchDoc: GATE (out), P12V, P12V_RTN, ANODE, CATHODE

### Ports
CH-EN, FAULT (in), GATE_DRV_HIGH (out), GND, P5V, P12V, RESETn (in)

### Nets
GND: C51.1 Q6.2(S) Q7.2(E) R90.1 U21.3(GND) ; port GND, sheet MOSFET HIGH Driver/P12V_RTN, sheet MOSFET HIGH Driver/CATHODE
P5V: C51.2 Q5.2(E) U21.5(VCC) ; port P5V
P12V: port P12V, sheet MOSFET HIGH Driver/P12V
CH-EN: R92.1 ; port CH-EN
FAULT: Q6.1(G) R90.2 ; port FAULT
GATE_DRV_HIGH: port GATE_DRV_HIGH, sheet MOSFET HIGH Driver/GATE
RESETn: U21.4(Y) ; port RESETn
NetQ5_1: Q5.1(B) R84.2
NetQ5_3: Q5.3(C) R76.1
NetQ6_3: Q6.3(D) R76.2 ; sheet MOSFET HIGH Driver/ANODE
NetQ7_1: Q7.1(B) R92.2
NetQ7_3: Q7.3(C) R84.1 U21.2(A)

Not connected (* = marked no-connect by the designer): U21 1(NC)*

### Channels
Designator/Interface Channel A/Solid State Switches/Short Circuit Logic Intergration: designators end in _A; ports CH-EN=CH-EN_Solid State Switches FAULT=FAULT-BUF_Solid State Switches GATE_DRV_HIGH=GATE_DRV_HIGH_Solid State Switches GND=ISO_RTN_Solid State Switches P5V=HV_P5V P12V=HV_P12V RESETn=RESETn_Solid State Switches
Designator/Interface Channel B/Solid State Switches/Short Circuit Logic Intergration: designators end in _B; ports CH-EN=CH-EN_Solid State Switches FAULT=FAULT-BUF_Solid State Switches GATE_DRV_HIGH=GATE_DRV_HIGH_Solid State Switches GND=ISO_RTN_Solid State Switches P5V=HV_P5V P12V=HV_P12V RESETn=RESETn_Solid State Switches
Designator/Interface Channel C/Solid State Switches/Short Circuit Logic Intergration: designators end in _C; ports CH-EN=CH-EN_Solid State Switches FAULT=FAULT-BUF_Solid State Switches GATE_DRV_HIGH=GATE_DRV_HIGH_Solid State Switches GND=ISO_RTN_Solid State Switches P5V=HV_P5V P12V=HV_P12V RESETn=RESETn_Solid State Switches
Designator/Interface Channel D/Solid State Switches/Short Circuit Logic Intergration: designators end in _D; ports CH-EN=CH-EN_Solid State Switches FAULT=FAULT-BUF_Solid State Switches GATE_DRV_HIGH=GATE_DRV_HIGH_Solid State Switches GND=ISO_RTN_Solid State Switches P5V=HV_P5V P12V=HV_P12V RESETn=RESETn_Solid State Switches

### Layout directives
net class P187_REF: GATE_DRV_HIGH_Solid State Switches

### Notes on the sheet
- (near Q5) Supplies 5V to MOSFET Driver anode when CH-EN is HIGH
- (near R76) LED Current Limiter
- If = 12.5mA
- (near U21) Pulls RESETn to GND when CH-EN is OFF
- HFE ~ 30 minimum
- Ib = ~882uA
- Ic = |6mA
- INA310 FAULT causes 5V MOSFET driver to turn off FAST
- INA310 will remain OFF until RESETn is driven LOW

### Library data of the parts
C51 = CMP-118-000468-2: WCAP-CSGP Multilayer Ceramic Chip Capacitor, General Purpose, size 0805, X7R, 100nF, 25VDC; Manufacturer: Wurth Elektronik; Dissipation Factor: 3.5%; Capacitance Tolerance: +/-10%; Insulation Resistance: 5GOhm; Case/Size Code: 0805; Technical Reference: X7R0805104K025DFCT10000
Q5 = CMP-013-00003-8: PNP General-Purpose Amplifier, 40 V, 0.2 A, -55 to 150 degC, 3-Pin SOT23, RoHS, Tape and Reel; Manufacturer: ON Semiconductor; Collector Emitter Saturation Voltage: -400mV; Power: 225mW; Current Rating: -200mA; Emitter Base Voltage (VEBO): 5V; Max Collector Current: 200mA; Collector-emitter Voltage-Max: 400mV; Max Breakdown Voltage: 40V; Max Power Dissipation: 300mW; Elements: 1; hFE Min: 80; Voltage Rating (DC): -40V; Frequency: 250MHz; OE Prototype: Yes
Q6 = CMP-013-00062-2: BSS138P Series 60 V 1.6 Ohm 350 mW 0.72 nC N-Channel SMT TrenchMOS FET - SOT-23; Drain to Source Resistance: 900mR; Turn-Off Delay Time: 9ns; Drain to Source Breakdown Voltage: 60V; Continuous Drain Current (ID): 360mA; Gate to Source Voltage (Vgs): 20V; Turn-On Delay Time: 2ns; Transistor Type: NMOS
Q7 = CMP-013-00007-8: General Purpose Transistor, NPN Silicon, 40 V, 0.2 A, -55 to 150 degC, 3-Pin SOT23, RoHS, Tape and Reel; Manufacturer: ON Semiconductor; Power: 225mW; Elements: 1; Voltage Rating (DC): 40V; Vce Max: 300mV; Frequency: 300MHz; hFE Min: 80; Current Rating: 200mA; Collector Base Voltage (VCBO): 60V; OE Prototype: Yes
R76 = CMP-009-01813-4: Generic 1% 294 Ohm 0805 Resistor; Decade: 100; Power: 0.125W; Voltage Rating: 150V
R84 R92 = CMP-009-01342-2: as R62 on sheet IN310_ISNS
R90 = CMP-009-01561-2: Generic 1% 49.9 kOhm 0805 Resistor; Decade: 10K; Power: 0.125W; Voltage Rating: 150V
U21 = CMP-016-00010-2: as U22 on sheet Solid_State_Switch

## Sheet Gate_Driver.SchDoc: MARS2 - IPB - Isolated Gate Driver
size 431 x 279 mm; Organization: ORGANIZATION; Address1: APPLIED PHYSICS LAB; Address2: UNIVERSITY OF WASHINGTON; Address3: 1013 NE 40TH STREET; Address4: SEATTLE, WA 98105; Revision: -; SheetNumber: 23; SheetTotal: 23; ENG_APP_DATE: --/--/--; DSN_APP_DATE: --/--/--; CHK_APP_DATE: --/--/--
Used 4 times, as channels Designator/Interface Channel A/Solid State Switches/Short Circuit Logic Intergration/MOSFET HIGH Driver, Designator/Interface Channel B/Solid State Switches/Short Circuit Logic Intergration/MOSFET HIGH Driver, Designator/Interface Channel C/Solid State Switches/Short Circuit Logic Intergration/MOSFET HIGH Driver, Designator/Interface Channel D/Solid State Switches/Short Circuit Logic Intergration/MOSFET HIGH Driver. Parts and nets are listed once, with the designators drawn on the sheet.
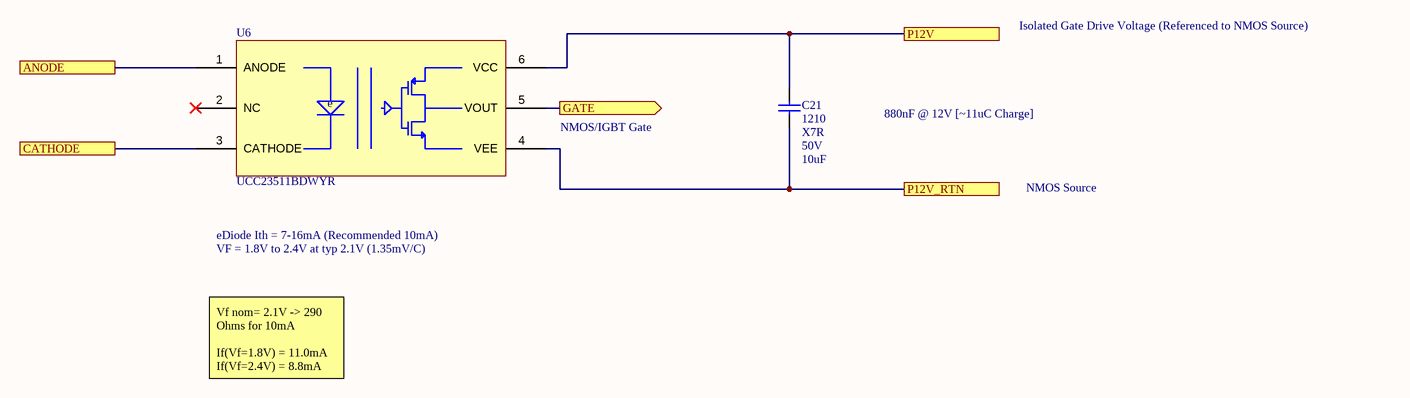
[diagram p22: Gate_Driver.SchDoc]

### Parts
C21  value 10uF  Case/Package: 1210  Dielectric: X7R  Voltage Rating: 50V  [CAPC3225X270X30ML30]  (hidden comment: Capacitor 10uF 10%, 50V, X7R, 1210)
U6  UCC23511BDWYR  [SOIC127P1150X355-6M]

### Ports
ANODE, CATHODE, GATE (out), P12V, P12V_RTN

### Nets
ANODE: U6.1(ANODE) ; port ANODE
CATHODE: U6.3(CATHODE) ; port CATHODE
GATE: U6.5(VOUT) ; port GATE
P12V: C21.2 U6.6(VCC) ; port P12V
P12V_RTN: C21.1 U6.4(VEE) ; port P12V_RTN

Not connected (* = marked no-connect by the designer): U6 2(NC)*

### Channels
Designator/Interface Channel A/Solid State Switches/Short Circuit Logic Intergration/MOSFET HIGH Driver: designators end in _A; ports ANODE=NetQ6_A_3 CATHODE=ISO_RTN_Solid State Switches GATE=GATE_DRV_HIGH_Solid State Switches P12V=HV_P12V P12V_RTN=ISO_RTN_Solid State Switches
Designator/Interface Channel B/Solid State Switches/Short Circuit Logic Intergration/MOSFET HIGH Driver: designators end in _B; ports ANODE=NetQ6_B_3 CATHODE=ISO_RTN_Solid State Switches GATE=GATE_DRV_HIGH_Solid State Switches P12V=HV_P12V P12V_RTN=ISO_RTN_Solid State Switches
Designator/Interface Channel C/Solid State Switches/Short Circuit Logic Intergration/MOSFET HIGH Driver: designators end in _C; ports ANODE=NetQ6_C_3 CATHODE=ISO_RTN_Solid State Switches GATE=GATE_DRV_HIGH_Solid State Switches P12V=HV_P12V P12V_RTN=ISO_RTN_Solid State Switches
Designator/Interface Channel D/Solid State Switches/Short Circuit Logic Intergration/MOSFET HIGH Driver: designators end in _D; ports ANODE=NetQ6_D_3 CATHODE=ISO_RTN_Solid State Switches GATE=GATE_DRV_HIGH_Solid State Switches P12V=HV_P12V P12V_RTN=ISO_RTN_Solid State Switches

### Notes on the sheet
- Isolated Gate Drive Voltage (Referenced to NMOS Source)
- 880nF @ 12V [
  1uC Charge]
- NMOS/IGBT Gate
- NMOS Source
- eDiode Ith = 7-16mA (Recommended 10mA)
- VF = 1.8V to 2.4V at typ 2.1V (1.35mV/C)
- Vf nom= 2.1V -> 290 Ohms for 10mA
  If(Vf=1.8V) = 11.0mA
  If(Vf=2.4V) = 8.8mA

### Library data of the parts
C21 = CMP-001-00184-10: Chip Capacitor, 10uF, 10%, 50 V, X7R 1210 (3225 Metric); Capacitor Type: Ceramic
U6 = CMP-015-00012-3: 5.7kVrms 1.5A/2A single-channel opto-compatible isolated gate driver with 8 & 12V UVLO options; UVLO: 8V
